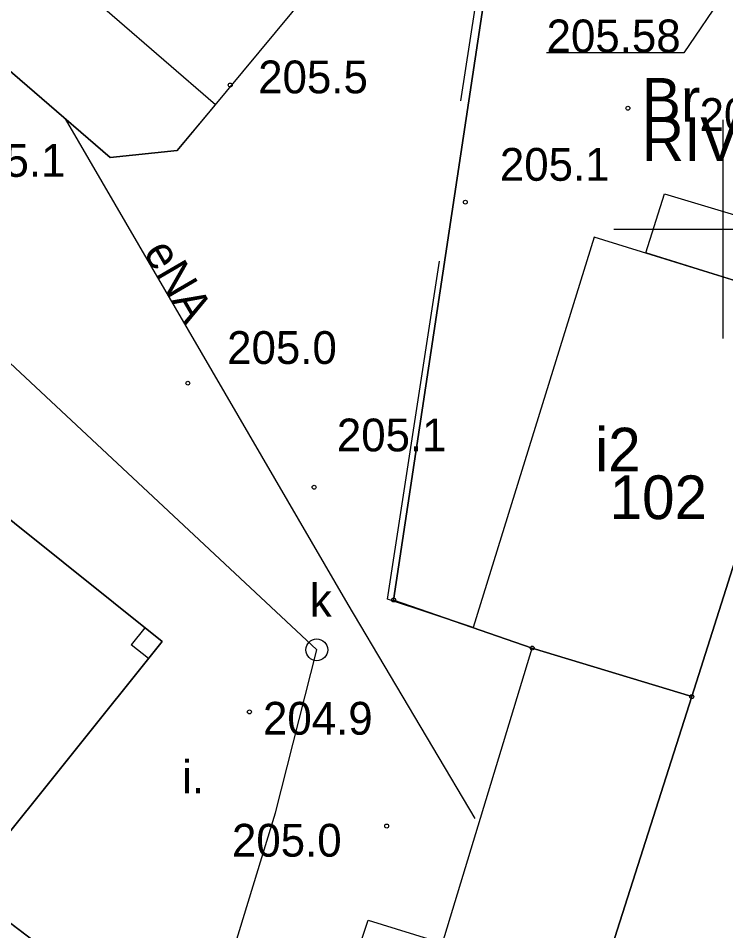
# Model space of a CAD drawing. Extents: x 6512606 to 6513006, y 6022524 to 6022728.
# Drawn here: x 6512783.87 to 6512800.06, y 6022633.96 to 6022654.83 of the extents above; entities that cross this region are included whole.
import ezdxf

# ---------------------------------------------------------------- set-up
doc = ezdxf.new("R2010")
doc.units = 0
for name, color, linetype in [('203-punkt graniczny', 7, 'Continuous'), ('209-oznaczenie konturu klasyfikacyjnego', 7, 'Continuous'), ('210-oznaczenie konturu użytku gruntowego', 7, 'Continuous'), ('217-kontur klasyfikacyjny', 7, 'Continuous'), ('218-kontur użytku gruntowego', 7, 'Continuous'), ('219-działka ewidencyjna', 7, 'Continuous'), ('312-budynek ewidencyjny', 7, 'Continuous'), ('312-oznaczenie budynku ewidencyjnego', 7, 'Continuous'), ('312-oznaczenie budynku ewidencyjnego-Atr117', 7, 'Continuous'), ('320-blok - kondygnacja nadziemna', 7, 'Continuous'), ('4', 7, 'Continuous'), ('Default', 7, 'Continuous'), ('inna budowla', 7, 'Continuous'), ('obszar utwardzony', 7, 'Continuous'), ('obszar utwardzony-Atr17', 7, 'Continuous'), ('ogrodzenie trwałe', 7, 'Continuous'), ('pikieta naturalna', 7, 'Continuous'), ('pikieta naturalna-Atr2', 7, 'Continuous'), ('przewód elektroenergetyczny (linia)', 7, 'Continuous'), ('przewód elektroenergetyczny (linia)-Atr1', 7, 'Continuous'), ('przewód kanalizacyjny (linia)', 7, 'Continuous'), ('punkt o określonej wysokości (sieć kanalizacyjna)-Atr2', 7, 'Continuous'), ('punkt wysokościowy naturalny', 7, 'Continuous'), ('punkt wysokościowy naturalny-Atr2', 7, 'Continuous'), ('wiata', 7, 'Continuous'), ('właz okrągły - siec kanalizacyjna (punkt)', 7, 'Continuous'), ('właz okrągły - siec kanalizacyjna (punkt)-Atr17', 7, 'Continuous')]:
    doc.layers.add(name, color=color, linetype=linetype)

# ---------------------------------------------------------------- blocks, each defined once
blk = doc.blocks.new('203')
at = {"layer": 'Default'}
blk.add_circle((0, 0), 0.45, dxfattribs=at)
blk = doc.blocks.new('US22')
at = {"layer": 'Default'}
blk.add_circle((0, 0), 2.5, dxfattribs=at)
blk = doc.blocks.new('PW01')
at = {"layer": 'Default'}
blk.add_circle((0, 0), 0.45, dxfattribs=at)
blk = doc.blocks.new('IB10')
at = {"layer": 'Default'}
for p, q in [((0, 0), (0, 5)), ((0, 5), (5, 5)), ((5, 0), (5, 5)), ((0, 0), (5, 0))]:
    blk.add_line(p, q, dxfattribs=at)

msp = doc.modelspace()

# ---------------------------------------------------------------- linework, layer by layer
at = {"layer": '217-kontur klasyfikacyjny'}
for points in [[(6512795.45, 6022661.39), (6512792.46, 6022641.52)], [(6512792.46, 6022641.52), (6512795.45, 6022661.39)], [(6512799.28, 6022639.31), (6512800.63, 6022643.56)], [(6512792.46, 6022641.52), (6512795.63, 6022640.42)], [(6512795.63, 6022640.42), (6512792.46, 6022641.52)], [(6512795.63, 6022640.42), (6512799.28, 6022639.31)], [(6512799.28, 6022639.31), (6512795.63, 6022640.42)], [(6512795.87, 6022628.65), (6512799.28, 6022639.31)]]:
    msp.add_lwpolyline(points, dxfattribs=at)
at = {"layer": '218-kontur użytku gruntowego'}
for points in [[(6512795.45, 6022661.39), (6512792.46, 6022641.52)], [(6512792.46, 6022641.52), (6512795.45, 6022661.39)], [(6512799.28, 6022639.31), (6512800.63, 6022643.56)], [(6512800.63, 6022643.56), (6512799.28, 6022639.31)], [(6512792.46, 6022641.52), (6512795.63, 6022640.42)], [(6512795.63, 6022640.42), (6512792.46, 6022641.52)], [(6512795.63, 6022640.42), (6512799.28, 6022639.31)], [(6512799.28, 6022639.31), (6512795.63, 6022640.42)], [(6512799.28, 6022639.31), (6512795.87, 6022628.65)], [(6512795.87, 6022628.65), (6512799.28, 6022639.31)]]:
    msp.add_lwpolyline(points, dxfattribs=at)
at = {"layer": '219-działka ewidencyjna'}
for points in [[(6512795.45, 6022661.39), (6512792.46, 6022641.52)], [(6512800.63, 6022643.56), (6512799.28, 6022639.31)], [(6512795.63, 6022640.42), (6512792.46, 6022641.52)], [(6512799.28, 6022639.31), (6512795.63, 6022640.42)], [(6512799.28, 6022639.31), (6512795.87, 6022628.65)]]:
    msp.add_lwpolyline(points, dxfattribs=at)
at = {"layer": '312-budynek ewidencyjny'}
for points in [[(6512795.77, 6022661.75), (6512787.51, 6022651.8)], [(6512785.97, 6022651.64), (6512777.31, 6022659.12)], [(6512787.51, 6022651.8), (6512785.97, 6022651.64)]]:
    msp.add_lwpolyline(points, dxfattribs=at)
for points in [[(6512800.63, 6022643.56), (6512802.13, 6022648.24), (6512802.04, 6022648.27), (6512797.05, 6022649.82), (6512794.28, 6022640.89), (6512795.63, 6022640.42), (6512799.28, 6022639.31)], [(6512795.63, 6022640.42), (6512799.28, 6022639.31), (6512794.05, 6022622.97), (6512788.71, 6022624.64), (6512791.88, 6022634.2), (6512793.58, 6022633.67)]]:
    msp.add_lwpolyline(points, close=True, dxfattribs=at)
at = {"layer": '320-blok - kondygnacja nadziemna'}
msp.add_lwpolyline([(6512787.51, 6022651.8), (6512788.38, 6022652.85), (6512778.92, 6022661.03), (6512777.42, 6022659.24), (6512777.31, 6022659.12), (6512785.97, 6022651.64)], close=True, dxfattribs=at)
at = {"layer": '4'}
for points in [[(6512795.45, 6022661.39), (6512792.46, 6022641.52)], [(6512800.63, 6022643.56), (6512799.28, 6022639.31)], [(6512795.63, 6022640.42), (6512792.46, 6022641.52)], [(6512799.28, 6022639.31), (6512795.63, 6022640.42)], [(6512799.28, 6022639.31), (6512795.87, 6022628.65)]]:
    msp.add_lwpolyline(points, dxfattribs=at)
at = {"layer": 'Default'}
for p, q in [((6512800, 6022647.5), (6512800, 6022652.5)), ((6512800, 6022647.5), (6512800, 6022652.5)), ((6512797.5, 6022650), (6512800, 6022650)), ((6512800, 6022650), (6512802.5, 6022650))]:
    msp.add_line(p, q, dxfattribs=at)
at = {"layer": 'inna budowla'}
for points in [[(6512798.66, 6022650.81), (6512802.47, 6022649.67), (6512802.04, 6022648.27), (6512798.23, 6022649.46)], [(6512767.02, 6022638.26), (6512783.18, 6022625.97), (6512787.3, 6022631.38), (6512771.14, 6022643.67)]]:
    msp.add_lwpolyline(points, close=True, dxfattribs=at)
at = {"layer": 'obszar utwardzony'}
msp.add_lwpolyline([(6512775.13, 6022653.27), (6512779.67, 6022649.83), (6512778.13, 6022647.8), (6512787.16, 6022640.57), (6512783.02, 6022635.41), (6512782.63, 6022634.93), (6512787.3, 6022631.38), (6512783.18, 6022625.97), (6512782.4, 6022624.88), (6512782.6, 6022624.74), (6512781.28, 6022622.94), (6512787.17, 6022619.72)], dxfattribs=at)
at = {"layer": 'ogrodzenie trwałe'}
for points in [[(6512794, 6022652.94), (6512795.26, 6022661.13)], [(6512792.32, 6022641.54), (6512793.51, 6022649.27)], [(6512794.28, 6022640.89), (6512792.32, 6022641.54)]]:
    msp.add_lwpolyline(points, dxfattribs=at)
at = {"layer": 'przewód elektroenergetyczny (linia)'}
msp.add_lwpolyline([(6512784.94, 6022652.53), (6512791.41, 6022641.42), (6512794.32, 6022636.52)], dxfattribs=at)
at = {"layer": 'przewód kanalizacyjny (linia)'}
for points in [[(6512780.05, 6022650.33), (6512790.7, 6022640.38)], [(6512784.81, 6022621.53), (6512786.17, 6022625.59), (6512788.31, 6022631.92), (6512789.76, 6022636.65), (6512790.7, 6022640.38)]]:
    msp.add_lwpolyline(points, dxfattribs=at)
at = {"layer": 'punkt o określonej wysokości (sieć kanalizacyjna)-Atr2'}
msp.add_lwpolyline([(6512800.02, 6022655.4), (6512799.1, 6022654.04), (6512795.959, 6022654.04)], dxfattribs=at)
at = {"layer": 'wiata'}
msp.add_lwpolyline([(6512769.62, 6022646.34), (6512783.02, 6022635.41), (6512787.16, 6022640.57), (6512778.13, 6022647.8), (6512775.89, 6022649.52), (6512773.2, 6022646.66), (6512770.59, 6022649.11)], close=True, dxfattribs=at)

# ---------------------------------------------------------------- block references
at = {"layer": '203-punkt graniczny', "xscale": 0.1, "yscale": 0.10000000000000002}
for p in [(6512792.46, 6022641.52), (6512795.63, 6022640.42), (6512799.28, 6022639.31)]:
    msp.add_blockref('203', p, dxfattribs=at)
at = {"layer": 'pikieta naturalna', "xscale": 0.1, "yscale": 0.10000000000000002}
for p in [(6512797.82, 6022652.77), (6512794.1, 6022650.62), (6512787.75, 6022646.48), (6512790.64, 6022644.1), (6512789.16, 6022638.96), (6512792.3, 6022636.35)]:
    msp.add_blockref('PW01', p, dxfattribs=at)
at = {"layer": 'punkt wysokościowy naturalny', "xscale": 0.1, "yscale": 0.10000000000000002}
msp.add_blockref('PW01', (6512788.72, 6022653.3), dxfattribs=at)
at = {"layer": 'wiata', "xscale": 0.1, "yscale": 0.10000000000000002, "rotation": 141.317}
msp.add_blockref('IB10', (6512787.16, 6022640.57), dxfattribs=at)
at = {"layer": 'właz okrągły - siec kanalizacyjna (punkt)', "xscale": 0.1, "yscale": 0.10000000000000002}
msp.add_blockref('US22', (6512790.7, 6022640.38), dxfattribs=at)

# ---------------------------------------------------------------- texts
at = {"layer": '209-oznaczenie konturu klasyfikacyjnego'}
msp.add_text('RIVb', height=1, dxfattribs=at).set_placement((6512798.14, 6022651.56))
at = {"layer": '210-oznaczenie konturu użytku gruntowego'}
msp.add_text('Br', height=1, dxfattribs=at).set_placement((6512798.14, 6022652.46))
at = {"layer": '312-oznaczenie budynku ewidencyjnego'}
msp.add_text('102', height=1, dxfattribs=at).set_placement((6512797.4, 6022643.37))
at = {"layer": '312-oznaczenie budynku ewidencyjnego-Atr117'}
msp.add_text('i2', height=1, dxfattribs=at).set_placement((6512797.072, 6022644.46))
at = {"layer": 'obszar utwardzony-Atr17'}
msp.add_text('i.', height=0.75, dxfattribs=at).set_placement((6512787.62, 6022637.1))
at = {"layer": 'pikieta naturalna-Atr2'}
for s, p in [('205.2', (6512799.46, 6022652.25)), ('205.1', (6512782.44, 6022651.2)), ('205.1', (6512794.89, 6022651.11)), ('205.0', (6512788.65, 6022646.92)), ('205.1', (6512791.16, 6022644.92)), ('204.9', (6512789.47, 6022638.44)), ('205.0', (6512788.76, 6022635.65))]:
    msp.add_text(s, height=0.75, dxfattribs=at).set_placement(p)
at = {"layer": 'przewód elektroenergetyczny (linia)-Atr1'}
msp.add_text('eNA', height=0.75, rotation=300.209, dxfattribs=at).set_placement((6512786.72, 6022649.48))
at = {"layer": 'punkt o określonej wysokości (sieć kanalizacyjna)-Atr2'}
msp.add_text('205.58', height=0.75, dxfattribs=at).set_placement((6512795.959, 6022654.048))
at = {"layer": 'punkt wysokościowy naturalny-Atr2'}
msp.add_text('205.5', height=0.75, dxfattribs=at).set_placement((6512789.36, 6022653.11))
at = {"layer": 'właz okrągły - siec kanalizacyjna (punkt)-Atr17'}
msp.add_text('k', height=0.75, dxfattribs=at).set_placement((6512790.54, 6022641.14))

doc.saveas('drawing.dxf')
